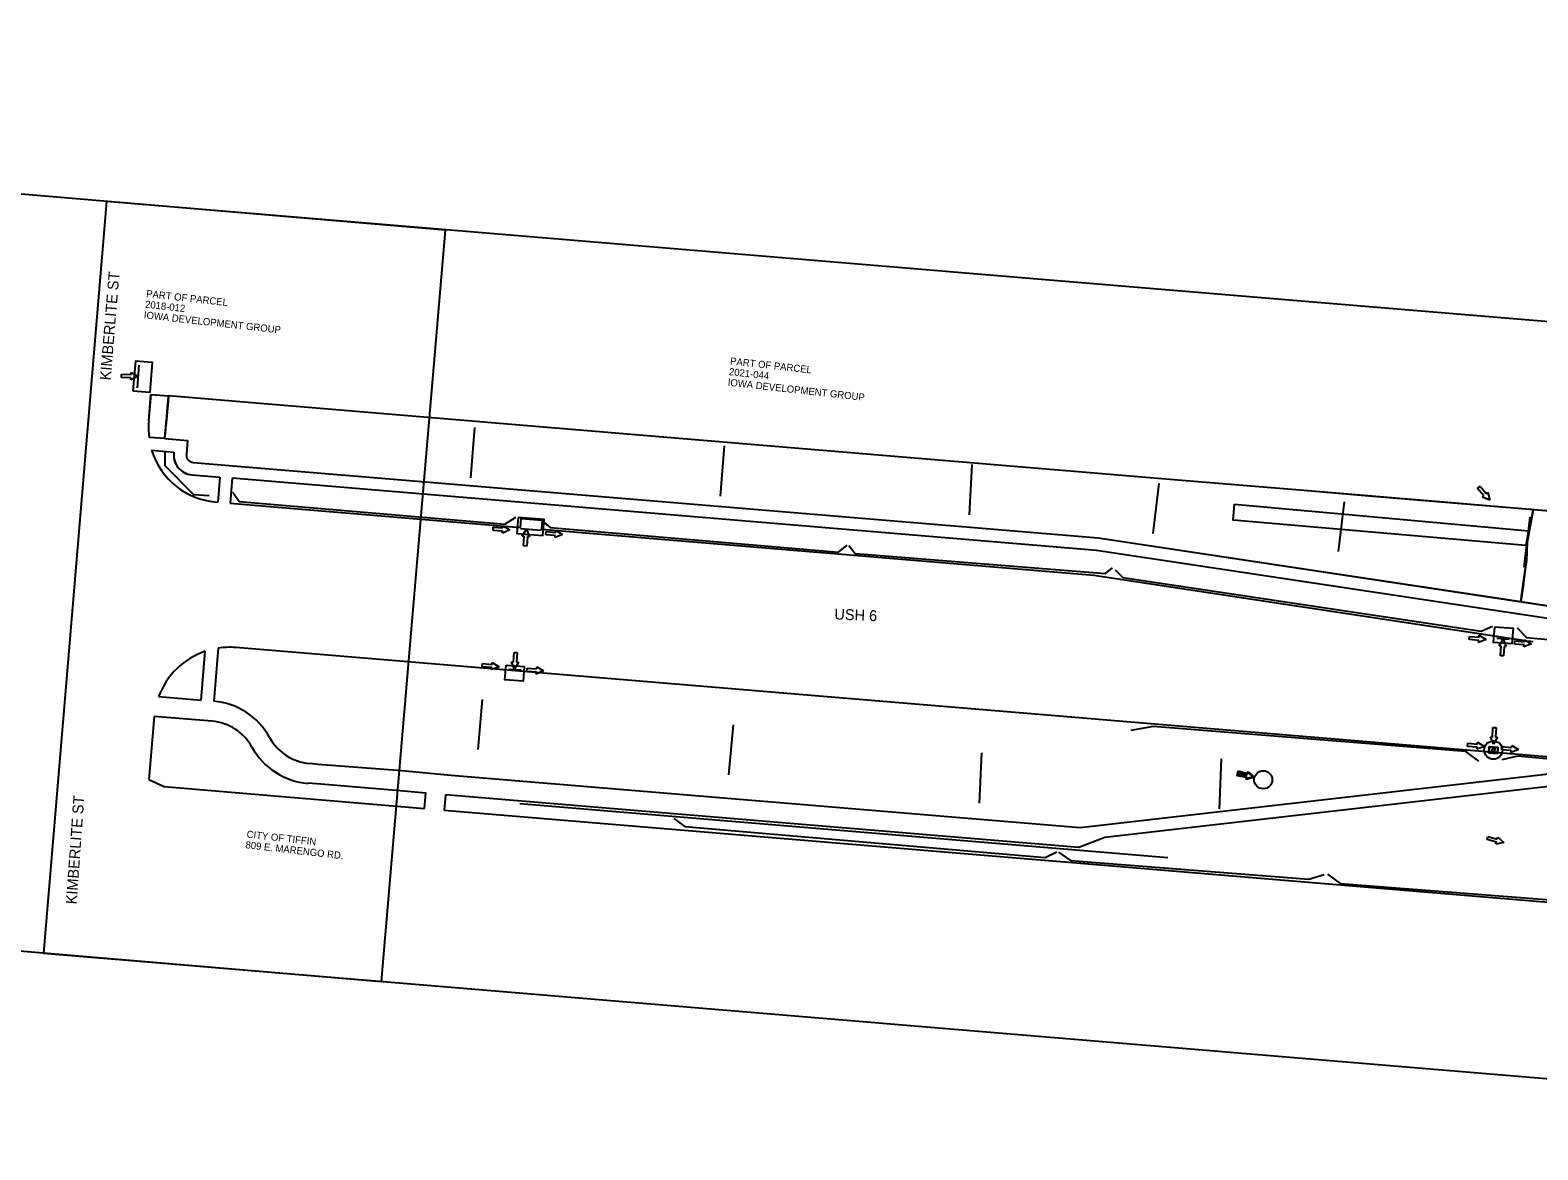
# Model space of a CAD drawing. Extents: x 20499990 to 20505779, y 7953198 to 7954399.
# Drawn here: x 20503208 to 20503807, y 7953540 to 7953986 of the extents above; entities that cross this region are included whole.
import ezdxf

# ---------------------------------------------------------------- set-up
doc = ezdxf.new("R2010")
doc.units = 0
for name, color, linetype in [('Building', 7, 'Continuous'), ('dsnCellElements', 7, 'Continuous'), ('ErosionControl', 7, 'Continuous'), ('NamedBoundary', 7, 'Continuous'), ('Seeding', 7, 'Continuous'), ('Text', 7, 'Continuous')]:
    doc.layers.add(name, color=color, linetype=linetype)

msp = doc.modelspace()

# ---------------------------------------------------------------- linework, layer by layer
at = {"layer": 'Building'}
for p, q in [((20503255.06, 7953830.18), (20503255.97, 7953840.64)), ((20503255.97, 7953840.67), (20503262.97, 7953840.03)), ((20503262.71, 7953837.72), (20503262.04, 7953829.76)), ((20503261.42, 7953823.06), (20503255.23, 7953823.58)), ((20503261.42, 7953823.06), (20503270.45, 7953822.3)), ((20503270.45, 7953822.3), (20503270, 7953816.87)), ((20503256.19, 7953818.48), (20503265.05, 7953817.73)), ((20503272.74, 7953813.62), (20503632.44, 7953783.61)), ((20503272.22, 7953808.65), (20503283.29, 7953807.73)), ((20503283.29, 7953807.73), (20503282.46, 7953797.77)), ((20503288.28, 7953807.31), (20503287.45, 7953797.35)), ((20503631.86, 7953778.64), (20503288.28, 7953807.31)), ((20503287.45, 7953797.35), (20503402.83, 7953787.72)), ((20503411.2, 7953787.02), (20503630.7, 7953768.71)), ((20503632.44, 7953783.61), (20503800.57, 7953758.23)), ((20503802.76, 7953774.63), (20503803, 7953781.9)), ((20503869.7, 7953742.74), (20503631.86, 7953778.64)), ((20503800.57, 7953758.23), (20503802.76, 7953774.63)), ((20503630.7, 7953768.71), (20503800.5, 7953743.08)), ((20503800.57, 7953758.23), (20503800.57, 7953758.23)), ((20503275.91, 7953719.04), (20503277.53, 7953738.5)), ((20503258.99, 7953720.46), (20503275.91, 7953719.04)), ((20503257.25, 7953712.57), (20503255.15, 7953687.47)), ((20503280.23, 7953710.66), (20503257.25, 7953712.57)), ((20503625.39, 7953668.38), (20503815.08, 7953690.11)), ((20503373.73, 7953689.35), (20503625.39, 7953668.38)), ((20503815.16, 7953685.08), (20503635.14, 7953664.47)), ((20503372.96, 7953681.4), (20503372.47, 7953675.36)), ((20503624.75, 7953660.41), (20503372.96, 7953681.38)), ((20503635.14, 7953664.47), (20503624.75, 7953660.41))]:
    msp.add_line(p, q, dxfattribs=at)
for points in [[(20503804.81, 7953794.82), (20503804.03, 7953794.88), (20503804.03, 7953794.88), (20503769.79, 7953797.74), (20503714.23, 7953802.38), (20503664.2, 7953806.55), (20503262.97, 7953840.03), (20503262.71, 7953837.72)], [(20503803, 7953781.9), (20503805.48, 7953794.76)], [(20503805.48, 7953794.76), (20503804.81, 7953794.82)], [(20503402.83, 7953787.72), (20503403.13, 7953791.3), (20503411.49, 7953790.6), (20503411.2, 7953787.02)], [(20503282.65, 7953739.74), (20503280.89, 7953718.63)], [(20504427.73, 7953645), (20504246.09, 7953660.16), (20503289.64, 7953739.98)], [(20503800.5, 7953743.08), (20503800.47, 7953742.8), (20503804.5, 7953742.46), (20503804.5, 7953742.47)], [(20503318.98, 7953693.96), (20503322.45, 7953693.64), (20503355.68, 7953691.08), (20503373.78, 7953689.41)], [(20503255.15, 7953687.47), (20503261.12, 7953684.65), (20503364.71, 7953676)], [(20503364.71, 7953676), (20503365.17, 7953682.12), (20503355.03, 7953683.03), (20503321.91, 7953685.81), (20503318.31, 7953686)], [(20503372.47, 7953675.36), (20503841.67, 7953636.21)]]:
    msp.add_lwpolyline(points, dxfattribs=at)
for centre, radius, start, end in [((20405466.7, 7962787.48), 98204.73, 354.7625797, 354.7725236), ((20503284.18, 7953827.64), 29.23, 175.01935, 187.98528), ((20502922.14, 7953858.12), 341.09, 354.09913, 355.22957), ((20503284.28, 7953827.09), 29.37, 197.04219, 266.45959), ((20503272.88, 7953816.55), 7.92, 171.36257, 265.22696), ((20503272.98, 7953816.61), 3, 175.18564, 265.23075), ((20503287.14, 7953710.08), 30, 108.69185, 159.76356), ((20503287.14, 7953710.08), 30, 85.22957, 98.61423), ((20503278.57, 7953690.73), 28, 28.78535, 85.23839), ((20503278.57, 7953690.73), 20, 28.78535, 85.23967), ((20503320.63, 7953713.84), 20, 208.78535, 265.23848), ((20503320.63, 7953713.84), 28, 208.78535, 265.23848)]:
    msp.add_arc(centre, radius, start, end, dxfattribs=at)
at = {"layer": 'dsnCellElements'}
for p, q in [((20503244.16, 7953847.41), (20503244.19, 7953848.68)), ((20503247.97, 7953847.31), (20503244.16, 7953847.41)), ((20503244.19, 7953848.68), (20503248, 7953848.58)), ((20503250.85, 7953847.87), (20503247.95, 7953846.52)), ((20503247.95, 7953846.52), (20503247.97, 7953847.31)), ((20503248, 7953848.58), (20503248.02, 7953849.38)), ((20503248.02, 7953849.38), (20503250.85, 7953847.87)), ((20503783.35, 7953803.27), (20503784.32, 7953804.1)), ((20503784.32, 7953804.1), (20503786.79, 7953801.19)), ((20503785.82, 7953800.37), (20503783.35, 7953803.27)), ((20503785.22, 7953799.85), (20503785.82, 7953800.37)), ((20503788.16, 7953798.6), (20503785.22, 7953799.85)), ((20503786.79, 7953801.19), (20503787.4, 7953801.71)), ((20503787.4, 7953801.71), (20503788.16, 7953798.6)), ((20503391.91, 7953786.57), (20503392, 7953787.84)), ((20503395.72, 7953786.3), (20503391.91, 7953786.57)), ((20503392, 7953787.84), (20503395.81, 7953787.57)), ((20503398.62, 7953786.74), (20503395.66, 7953785.51)), ((20503395.66, 7953785.51), (20503395.72, 7953786.3)), ((20503395.81, 7953787.57), (20503395.86, 7953788.37)), ((20503395.86, 7953788.37), (20503398.62, 7953786.74)), ((20503403.56, 7953784.29), (20503405.21, 7953787.03)), ((20503405.21, 7953787.03), (20503406.42, 7953784.07)), ((20503412.87, 7953784.81), (20503412.98, 7953786.08)), ((20503412.98, 7953786.08), (20503416.78, 7953785.77)), ((20503416.78, 7953785.77), (20503416.84, 7953786.57)), ((20503416.84, 7953786.57), (20503419.58, 7953784.91)), ((20503404.36, 7953784.23), (20503403.56, 7953784.29)), ((20503404.07, 7953780.42), (20503404.36, 7953784.23)), ((20503405.34, 7953780.33), (20503404.07, 7953780.42)), ((20503405.63, 7953784.13), (20503405.34, 7953780.33)), ((20503406.42, 7953784.07), (20503405.63, 7953784.13)), ((20503416.68, 7953784.5), (20503412.87, 7953784.81)), ((20503419.58, 7953784.91), (20503416.62, 7953783.71)), ((20503416.62, 7953783.71), (20503416.68, 7953784.5)), ((20503779.99, 7953743.16), (20503780.1, 7953744.43)), ((20503780.1, 7953744.43), (20503783.9, 7953744.08)), ((20503783.9, 7953744.08), (20503783.98, 7953744.87)), ((20503783.98, 7953744.87), (20503786.7, 7953743.18)), ((20503400.01, 7953734.25), (20503400.26, 7953738.06)), ((20503400.01, 7953734.25), (20503400.26, 7953738.06)), ((20503400.26, 7953738.06), (20503401.53, 7953737.98)), ((20503400.26, 7953738.06), (20503401.53, 7953737.98)), ((20503401.53, 7953737.98), (20503401.28, 7953734.17)), ((20503401.53, 7953737.98), (20503401.28, 7953734.17)), ((20503783.79, 7953742.81), (20503779.99, 7953743.16)), ((20503786.7, 7953743.18), (20503783.72, 7953742.02)), ((20503783.72, 7953742.02), (20503783.79, 7953742.81)), ((20503791.85, 7953740.6), (20503793.47, 7953743.36)), ((20503792.64, 7953740.55), (20503791.85, 7953740.6)), ((20503792.4, 7953736.74), (20503792.64, 7953740.55)), ((20503793.47, 7953743.36), (20503794.71, 7953740.41)), ((20503793.91, 7953740.46), (20503793.67, 7953736.65)), ((20503794.71, 7953740.41), (20503793.91, 7953740.46)), ((20503798.02, 7953741.36), (20503798.13, 7953742.62)), ((20503801.82, 7953741.01), (20503798.02, 7953741.36)), ((20503798.13, 7953742.62), (20503801.93, 7953742.28)), ((20503804.73, 7953741.39), (20503801.75, 7953740.22)), ((20503801.75, 7953740.22), (20503801.82, 7953741.01)), ((20503801.93, 7953742.28), (20503802, 7953743.07)), ((20503802, 7953743.07), (20503804.73, 7953741.39)), ((20503387.64, 7953732.35), (20503387.76, 7953733.61)), ((20503387.64, 7953732.35), (20503387.76, 7953733.61)), ((20503391.44, 7953731.99), (20503387.64, 7953732.35)), ((20503391.44, 7953731.99), (20503387.64, 7953732.35)), ((20503387.76, 7953733.61), (20503391.56, 7953733.26)), ((20503387.76, 7953733.61), (20503391.56, 7953733.26)), ((20503394.35, 7953732.36), (20503391.37, 7953731.2)), ((20503394.35, 7953732.36), (20503391.37, 7953731.2)), ((20503391.37, 7953731.2), (20503391.44, 7953731.99)), ((20503391.37, 7953731.2), (20503391.44, 7953731.99)), ((20503391.56, 7953733.26), (20503391.64, 7953734.05)), ((20503391.56, 7953733.26), (20503391.64, 7953734.05)), ((20503391.64, 7953734.05), (20503394.35, 7953732.36)), ((20503391.64, 7953734.05), (20503394.35, 7953732.36)), ((20503400.45, 7953731.36), (20503399.22, 7953734.31)), ((20503399.22, 7953734.31), (20503400.01, 7953734.25)), ((20503400.45, 7953731.36), (20503399.22, 7953734.31)), ((20503399.22, 7953734.31), (20503400.01, 7953734.25)), ((20503402.07, 7953734.12), (20503400.45, 7953731.36)), ((20503402.07, 7953734.12), (20503400.45, 7953731.36)), ((20503401.28, 7953734.17), (20503402.07, 7953734.12)), ((20503401.28, 7953734.17), (20503402.07, 7953734.12)), ((20503409.23, 7953731.5), (20503409.29, 7953732.3)), ((20503409.23, 7953731.5), (20503409.29, 7953732.3)), ((20503409.29, 7953732.3), (20503412.04, 7953730.67)), ((20503409.29, 7953732.3), (20503412.04, 7953730.67)), ((20503793.67, 7953736.65), (20503792.4, 7953736.74)), ((20503405.34, 7953730.5), (20503405.43, 7953731.77)), ((20503405.34, 7953730.5), (20503405.43, 7953731.77)), ((20503409.14, 7953730.23), (20503405.34, 7953730.5)), ((20503409.14, 7953730.23), (20503405.34, 7953730.5)), ((20503405.43, 7953731.77), (20503409.23, 7953731.5)), ((20503405.43, 7953731.77), (20503409.23, 7953731.5)), ((20503412.04, 7953730.67), (20503409.09, 7953729.44)), ((20503412.04, 7953730.67), (20503409.09, 7953729.44)), ((20503409.09, 7953729.44), (20503409.14, 7953730.23)), ((20503409.09, 7953729.44), (20503409.14, 7953730.23)), ((20503789.2, 7953704.39), (20503789.43, 7953708.2)), ((20503789.43, 7953708.2), (20503790.7, 7953708.12)), ((20503790.7, 7953708.12), (20503790.47, 7953704.31)), ((20503779.3, 7953700.68), (20503779.43, 7953701.95)), ((20503779.43, 7953701.95), (20503783.23, 7953701.55)), ((20503783.23, 7953701.55), (20503783.31, 7953702.34)), ((20503783.31, 7953702.34), (20503786.01, 7953700.62)), ((20503789.66, 7953701.5), (20503788.4, 7953704.44)), ((20503788.4, 7953704.44), (20503789.2, 7953704.39)), ((20503791.26, 7953704.27), (20503789.66, 7953701.5)), ((20503790.47, 7953704.31), (20503791.26, 7953704.27)), ((20503783.1, 7953700.29), (20503779.3, 7953700.68)), ((20503786.01, 7953700.62), (20503783.01, 7953699.5)), ((20503783.01, 7953699.5), (20503783.1, 7953700.29)), ((20503792.93, 7953699.3), (20503793.03, 7953700.57)), ((20503796.73, 7953698.99), (20503792.93, 7953699.3)), ((20503793.03, 7953700.57), (20503796.83, 7953700.26)), ((20503799.64, 7953699.4), (20503796.67, 7953698.2)), ((20503796.67, 7953698.2), (20503796.73, 7953698.99)), ((20503796.83, 7953700.26), (20503796.9, 7953701.05)), ((20503796.9, 7953701.05), (20503799.64, 7953699.4)), ((20503687.76, 7953688.95), (20503687.99, 7953690.2)), ((20503687.86, 7953689.76), (20503688.21, 7953690.99)), ((20503687.99, 7953690.2), (20503691.74, 7953689.49)), ((20503688.21, 7953690.99), (20503691.88, 7953689.94)), ((20503691.74, 7953689.49), (20503691.89, 7953690.27)), ((20503691.88, 7953689.94), (20503692.1, 7953690.71)), ((20503691.89, 7953690.27), (20503694.44, 7953688.33)), ((20503692.1, 7953690.71), (20503694.46, 7953688.55)), ((20503691.51, 7953688.24), (20503687.76, 7953688.95)), ((20503691.54, 7953688.72), (20503687.86, 7953689.76)), ((20503691.32, 7953687.95), (20503691.54, 7953688.72)), ((20503694.46, 7953688.55), (20503691.32, 7953687.95)), ((20503694.44, 7953688.33), (20503691.36, 7953687.46)), ((20503691.36, 7953687.46), (20503691.51, 7953688.24)), ((20503787.11, 7953663.62), (20503787.46, 7953664.84)), ((20503790.78, 7953662.57), (20503787.11, 7953663.62)), ((20503787.46, 7953664.84), (20503791.13, 7953663.8)), ((20503790.56, 7953661.81), (20503790.78, 7953662.57)), ((20503793.7, 7953662.4), (20503790.56, 7953661.81)), ((20503791.13, 7953663.8), (20503791.34, 7953664.56)), ((20503791.34, 7953664.56), (20503793.7, 7953662.4))]:
    msp.add_line(p, q, dxfattribs=at)
at = {"layer": 'ErosionControl'}
for p, q in [((20503250.61, 7953843.3), (20503251.18, 7953852.28)), ((20503383.16, 7953807.54), (20503384.69, 7953827.49)), ((20503482.34, 7953800.22), (20503483.96, 7953820.16)), ((20503581.28, 7953792.78), (20503582.36, 7953812.75)), ((20503654.34, 7953785.33), (20503656.7, 7953805.19)), ((20503728.05, 7953778.12), (20503730.41, 7953797.98)), ((20503801.82, 7953771.97), (20503804.19, 7953791.83)), ((20503411.05, 7953786.52), (20503402.79, 7953787.23)), ((20503802.16, 7953770.12), (20503801.83, 7953767.69)), ((20503801.39, 7953764.33), (20503801.05, 7953761.81)), ((20503801.55, 7953765.59), (20503801.39, 7953764.33)), ((20503801.05, 7953761.81), (20503800.57, 7953758.23)), ((20503800.57, 7953758.23), (20503870.28, 7953747.71)), ((20503795.93, 7953743.21), (20503790.95, 7953743.63)), ((20503398.14, 7953731.44), (20503403.12, 7953731.05)), ((20503386.01, 7953699.4), (20503387.67, 7953719.33)), ((20503485.6, 7953689.31), (20503487.48, 7953709.22)), ((20503585.28, 7953678.08), (20503586.28, 7953698.06)), ((20503787.96, 7953700.2), (20503788.12, 7953700.18)), ((20503788.12, 7953700.18), (20503788.31, 7953700.34)), ((20503788.32, 7953700.51), (20503788.31, 7953700.34)), ((20503790.86, 7953697.87), (20503790.87, 7953698.03)), ((20503791.05, 7953698.19), (20503790.87, 7953698.03)), ((20503791.22, 7953698.17), (20503791.05, 7953698.19)), ((20503680.78, 7953675.69), (20503681.58, 7953695.67)), ((20503402.54, 7953677.92), (20503660.17, 7953656.46))]:
    msp.add_line(p, q, dxfattribs=at)
for points in [[(20503248.78, 7953842.04), (20503255.63, 7953841.49), (20503256.58, 7953853.37), (20503249.73, 7953853.92)], [(20503686.75, 7953796.98), (20503803.61, 7953786.46), (20503802.53, 7953780.55), (20503686.1, 7953790.6)], [(20503401.89, 7953791.74), (20503401.38, 7953785.31), (20503411.76, 7953784.49), (20503412.27, 7953790.91)], [(20503790.05, 7953748.14), (20503789.57, 7953742.15), (20503797.12, 7953741.56), (20503797.59, 7953747.54)], [(20503397.12, 7953733.02), (20503404.35, 7953732.45), (20503403.88, 7953726.55), (20503396.65, 7953727.13)], [(20503787.79, 7953698.11), (20503791.19, 7953697.84), (20503791.39, 7953700.26), (20503787.98, 7953700.53)], [(20503787.98, 7953700.53), (20503791.39, 7953700.26), (20503791.19, 7953697.84), (20503787.79, 7953698.11)], [(20503787.96, 7953698.1), (20503787.79, 7953698.11), (20503787.82, 7953698.45), (20503787.98, 7953698.43)], [(20503788.12, 7953700.18), (20503787.96, 7953700.2), (20503787.98, 7953700.53), (20503788.15, 7953700.52)], [(20503789.13, 7953699.73), (20503790.13, 7953699.65), (20503790.05, 7953698.64), (20503789.04, 7953698.72)], [(20503791.19, 7953697.84), (20503791.03, 7953697.85), (20503791.05, 7953698.19), (20503791.22, 7953698.17)], [(20503791.36, 7953699.92), (20503791.19, 7953699.94), (20503791.22, 7953700.27), (20503791.39, 7953700.26)]]:
    msp.add_lwpolyline(points, close=True, dxfattribs=at)
for points in [[(20503261.42, 7953817.64), (20503261.42, 7953812.32), (20503272.78, 7953800.87), (20503279.01, 7953800.5)], [(20503288.53, 7953801.78), (20503291.01, 7953798.03), (20503396.63, 7953789.05), (20503401.03, 7953791.89)], [(20503826.97, 7953797.99), (20503817.52, 7953798.78), (20503817.1, 7953793.79), (20503805.48, 7953794.76), (20503803, 7953781.9), (20503802.76, 7953774.63), (20503802.16, 7953770.12)], [(20503410.28, 7953791.25), (20503414.58, 7953787.76), (20503529.21, 7953777.92), (20503532.65, 7953780.67)], [(20503533.39, 7953780.53), (20503535.86, 7953777.32), (20503635.37, 7953769.38), (20503638.23, 7953771.67)], [(20503639.23, 7953770.95), (20503642.24, 7953767.8), (20503784.8, 7953746.47), (20503789.24, 7953748.47)], [(20503799, 7953747.79), (20503802.78, 7953744.01), (20503869.88, 7953737.71), (20503875.04, 7953740.68)], [(20503783.76, 7953694.85), (20503778.59, 7953698.66), (20503654.41, 7953708.55), (20503645.46, 7953707.03)], [(20503949.49, 7953681.28), (20503945.16, 7953684.46), (20503872.39, 7953690.02), (20503799.21, 7953696.72), (20503792.9, 7953695.34)], [(20503463.85, 7953672.01), (20503468.16, 7953668.74), (20503611.47, 7953656.49), (20503616.04, 7953658.67)], [(20503616.66, 7953658.55), (20503621.54, 7953655.33), (20503716.18, 7953647.84), (20503722.36, 7953649.74)], [(20503723.64, 7953649.88), (20503728.66, 7953646.17), (20503849.78, 7953636.69), (20503859.63, 7953640.03)]]:
    msp.add_lwpolyline(points, dxfattribs=at)
for centre, radius in [((20503789.59, 7953699.19), 3.63), ((20503698.09, 7953687.39), 3.6)]:
    msp.add_circle(centre, radius, dxfattribs=at)
msp.add_arc((20503798.86, 7953767.02), 3.05, 332.11126, 12.72196, dxfattribs=at)
at = {"layer": 'NamedBoundary'}
for points in [[(20502435.82, 7953985.54), (20502410.46, 7953686.62), (20503347.59, 7953607.1), (20503372.96, 7953906.03)], [(20503238.22, 7953917.37), (20503213.27, 7953618.41), (20504150.52, 7953540.19), (20504175.47, 7953839.15)]]:
    msp.add_lwpolyline(points, close=True, dxfattribs=at)
at = {"layer": 'Seeding'}
for p, q in [((20503255.06, 7953830.18), (20503255.94, 7953840.62)), ((20503255.94, 7953840.64), (20503262.9, 7953840.04)), ((20503262.23, 7953832.05), (20503261.9, 7953828.05)), ((20503261.42, 7953823.06), (20503255.23, 7953823.58)), ((20503261.42, 7953823.06), (20503270.45, 7953822.3)), ((20503270.45, 7953822.3), (20503270, 7953816.87)), ((20503256.19, 7953818.48), (20503265.05, 7953817.73)), ((20503272.74, 7953813.62), (20503632.44, 7953783.61)), ((20503272.32, 7953808.65), (20503283.29, 7953807.73)), ((20503283.29, 7953807.73), (20503282.46, 7953797.77)), ((20503288.28, 7953807.31), (20503287.45, 7953797.35)), ((20503631.86, 7953778.64), (20503288.28, 7953807.31)), ((20503287.45, 7953797.35), (20503402.83, 7953787.72)), ((20503411.2, 7953787.02), (20503630.7, 7953768.71)), ((20503632.44, 7953783.61), (20503870.28, 7953747.71)), ((20503869.7, 7953742.74), (20503631.86, 7953778.64)), ((20503630.7, 7953768.71), (20503801.38, 7953742.94)), ((20503275.91, 7953719.04), (20503277.53, 7953738.5)), ((20503258.99, 7953720.46), (20503275.91, 7953719.04)), ((20503257.25, 7953712.57), (20503255.15, 7953687.47)), ((20503280.23, 7953710.66), (20503257.25, 7953712.57)), ((20503625.39, 7953668.38), (20503815.08, 7953690.11)), ((20503373.73, 7953689.35), (20503625.39, 7953668.38)), ((20503815.16, 7953685.08), (20503635.14, 7953664.47)), ((20503372.96, 7953681.4), (20503372.47, 7953675.36)), ((20503624.75, 7953660.41), (20503372.96, 7953681.38)), ((20503635.14, 7953664.47), (20503624.75, 7953660.41))]:
    msp.add_line(p, q, dxfattribs=at)
for points in [[(20503826.97, 7953797.99), (20503817.52, 7953798.78), (20503817.1, 7953793.79), (20503740.06, 7953800.22), (20503714.23, 7953802.38), (20503664.2, 7953806.55), (20503262.97, 7953840.03), (20503262.23, 7953832.05)], [(20503402.83, 7953787.72), (20503403.13, 7953791.3), (20503411.49, 7953790.6), (20503411.2, 7953787.02)], [(20503282.65, 7953739.74), (20503280.89, 7953718.63)], [(20504427.73, 7953645), (20504246.09, 7953660.16), (20503289.64, 7953739.98)], [(20503801.38, 7953742.94), (20503801.36, 7953742.73), (20503805.31, 7953742.4), (20503805.31, 7953742.35)], [(20503318.98, 7953693.96), (20503322.45, 7953693.64), (20503355.68, 7953691.08), (20503373.78, 7953689.41)], [(20503255.15, 7953687.47), (20503261.12, 7953684.65), (20503364.71, 7953676)], [(20503364.71, 7953676), (20503365.17, 7953682.12), (20503355.03, 7953683.03), (20503321.91, 7953685.81), (20503318.31, 7953686)], [(20503372.47, 7953675.36), (20503841.67, 7953636.21), (20503840.45, 7953626.27), (20503876.58, 7953623.26)]]:
    msp.add_lwpolyline(points, dxfattribs=at)
for centre, radius, start, end in [((20502401.63, 7953906.74), 863.85, 354.44118, 355.57161), ((20503284.95, 7953827.66), 30, 175.18564, 187.81899), ((20503073.06, 7953843.81), 189.5, 353.71293, 355.22957), ((20503284.28, 7953827.09), 29.37, 197.04219, 266.45959), ((20503272.99, 7953816.63), 8.01, 172.07045, 265.23014), ((20503272.98, 7953816.61), 3, 175.18564, 265.23075), ((20503287.14, 7953710.08), 30, 108.69185, 159.76356), ((20503287.14, 7953710.08), 30, 85.22957, 98.61423), ((20503278.57, 7953690.73), 28, 28.78535, 85.23839), ((20503278.57, 7953690.73), 20, 28.78535, 85.23967), ((20503320.63, 7953713.84), 20, 208.78535, 265.23848), ((20503320.63, 7953713.84), 28, 208.78535, 265.23848)]:
    msp.add_arc(centre, radius, start, end, dxfattribs=at)

# ---------------------------------------------------------------- texts
at = {"layer": 'Text'}
for s, height, rotation, p in [('KIMBERLITE ST', 4.32, 85.27579, (20503239.9, 7953846.15)), ('PART OF PARCEL', 2.8346, 353.65909, (20503253.93, 7953879.39)), ('2018-012', 2.835, 353.65909, (20503253.46, 7953875.17)), ('IOWA DEVELOPMENT GROUP', 2.8346, 353.65909, (20503252.99, 7953870.94)), ('PART OF PARCEL', 2.8346, 353.65909, (20503486.06, 7953852.59)), ('IOWA DEVELOPMENT GROUP', 2.8346, 353.65909, (20503485.12, 7953844.14)), ('2021-044', 2.835, 353.65909, (20503485.59, 7953848.37)), ('USH 6', 4.32, 357.50172, (20503527.54, 7953751.17)), ('KIMBERLITE ST', 4.32, 85.95271, (20503226.4, 7953637.74)), ('CITY OF TIFFIN', 2.8346, 353.49015, (20503293.86, 7953664.42)), ('809 E. MARENGO RD.', 2.8346, 353.49015, (20503293.38, 7953660.19))]:
    msp.add_text(s, height=height, rotation=rotation, dxfattribs=at).set_placement(p)

doc.saveas('drawing.dxf')
